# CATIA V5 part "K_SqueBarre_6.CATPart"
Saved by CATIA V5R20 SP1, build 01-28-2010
Part number: squelette_barre_6
Publications: "Point.1", "Point.2", "Droite.1", "Point.3", "Plan.1", "Droite.2", "Droite.3", "Droite.4", "Point.4"
Bounding box of the stored display mesh (mm): x 0 to 0, y 0 to 20, z 0 to 45
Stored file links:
  G:\Khaled_CFAO_2011\ST2M\ST2M_GR2\gcausse\Khaled\CAD_ThinkMotion\K_SqueBarre_6.CATPart
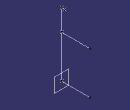
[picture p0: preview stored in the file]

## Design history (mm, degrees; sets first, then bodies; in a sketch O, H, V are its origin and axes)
Set1
  Point1: (0, 0, 0)
  Point2: (0, 0, 30)
  Line1: type PtPt, FirstPoint Point1, SecondPoint Point2, End 15
  Point3: (0, 0, 45)
  Plane1: type Offset, RefPlane zx-plane, Offset 0
  Line2: type PtDir, RefPoint Point1, Direction Plane1, Start 0, End 20
  Line3: type PtDir, RefPoint Point2, Direction Plane1, Start 0, End 20
  Line4: type PtDir, RefPoint Point3, Direction Plane1, Start 0, End 2
  Point4: (0, 2, 45)
Body1 (main body)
